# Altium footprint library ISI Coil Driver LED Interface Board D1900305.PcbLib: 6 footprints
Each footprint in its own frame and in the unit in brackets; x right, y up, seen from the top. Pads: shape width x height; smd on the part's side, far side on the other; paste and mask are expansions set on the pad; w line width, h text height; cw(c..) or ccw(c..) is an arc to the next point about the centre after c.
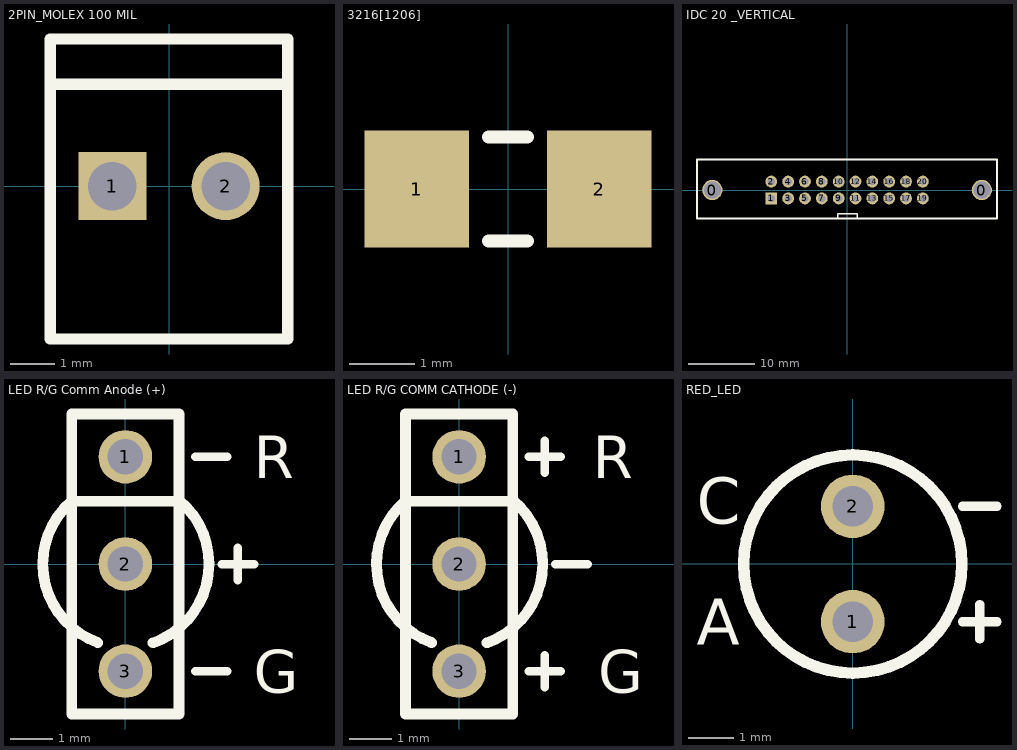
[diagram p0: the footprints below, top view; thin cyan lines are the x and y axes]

## 2PIN_MOLEX 100 MIL [mil]
pads (2):
  rect 60x60 hole 43: 1(-50,0)
  round 60 hole 43: 2(50,0)
Top Overlay:
  lines w10: -105,90 105,90 ; -105,-135 105,-135 105,130 -105,130 -105,-135
3D body "MOLEX 2pin 2.54mm (0022112022).stp": height 420.5, standoff -139.5, extent -97.01,-128.01 96.99,121.99

## 3216[1206] [mm] "Chip Resistor; Body 3.2 x 1.6 mm (LxW typ)"
height 2.54
pads (2):
  rect 1.6x1.8 smd: 1(-1.4,0) 2(1.4,0)
Top Overlay:
  lines w0.2: -0.3,-0.8 0.3,-0.8 ; -0.3,0.8 0.3,0.8
3D body "RES 1206 (3216).step": height 0.55, standoff 0, extent -1.6,-0.8 1.6,0.8

## IDC 20 _VERTICAL [mil]
pads (22):
  round 120 hole 100: 0(-800,0) 0(800,0)
  rect 70x70 hole 43: 1(-450,-50)
  round 70 hole 43: 2(-450,50) 3(-350,-50) 4(-350,50) 5(-250,-50) 6(-250,50) 7(-150,-50) 8(-150,50) 9(-50,-50) 10(-50,50) 11(50,-50) 12(50,50) 13(150,-50) 14(150,50) 15(250,-50) 16(250,50) 17(350,-50) 18(350,50) 19(450,-50) 20(450,50)
Top Overlay:
  lines w10: -55,-170 -55,-140 40,-140 60,-140 60,-170
  lines w12: -891,-170 890,-170 890,182 -891,182 -891,-170
3D body "Amph 20POS 2.54mm (71918-120LF).stp": height 1043.74, standoff -136.9, extent -880.92,-159 878.92,171.71

## LED R/G Comm Anode (+) [mil]
pads (3):
  round 50 hole 33: 1(0,100) 2(0,0) 3(0,-100)
Top Overlay:
  lines w8: 45,58.57 50.43,59.51 ; 65,-100 95,-100 ; 65,100 95,100 ; 90,-0.08 120,-0.08 ; 105,-15 105,15
  lines w10: -50.5,58.5 50.43,58.5 ; -50.5,58.57 ccw(c0.93,-0.08) -25.69,-73.39 ; 25.77,-73.62 ccw(c0,0) 50.43,59.51 ; -50,-140 -50,140 50,140 50,-140 -50,-140
  text "G" at 120,-120 h39.37
  text "R" at 120,80 h39.37
3D body "LED 3mmBiColor (SSL-LX3059IGW).STEP": height 305, standoff -90, extent -79.72,-110 79.72,110

## LED R/G COMM CATHODE (-) [mil]
pads (3):
  round 50 hole 33: 1(0,100) 2(0,0) 3(0,-100)
Top Overlay:
  lines w8: 45,58.57 50.43,59.51 ; 65,-100 95,-100 ; 65,100 95,100 ; 80,-115 80,-85 ; 80,85 80,115 ; 90,-0.08 120,-0.08
  lines w10: -50.5,58.5 50.43,58.5 ; -50.5,58.57 ccw(c0.93,-0.08) -25.69,-73.39 ; 25.77,-73.62 ccw(c0,0) 50.43,59.51 ; -50,-140 50,-140 50,140 -50,140 -50,-140
  text "R" at 125,80 h39.37
  text "G" at 130,-120 h39.37
3D body "LED 3mmBiColor (SSL-LX3059IGW).STEP": height 305, standoff -90, extent -79.72,-110 79.72,110

## RED_LED [mm]
pads (2):
  round 1.4 hole 0.9: 1(0,-1.27) 2(0,1.27)
Top Overlay:
  circle w0.254: c0,0 r2.4
  lines w0.203: 2.413,-1.27 3.175,-1.27 ; 2.413,1.27 3.175,1.27 ; 2.794,-1.651 2.794,-0.889
  text "C" at -3.429,0.889 h1.02
  text "A" at -3.429,-1.778 h1.02
3D body "LED 3mm T-1 (WP710A10).STEP": height 7.55, standoff -24.05, extent -1.6,-1.62 1.6,1.62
